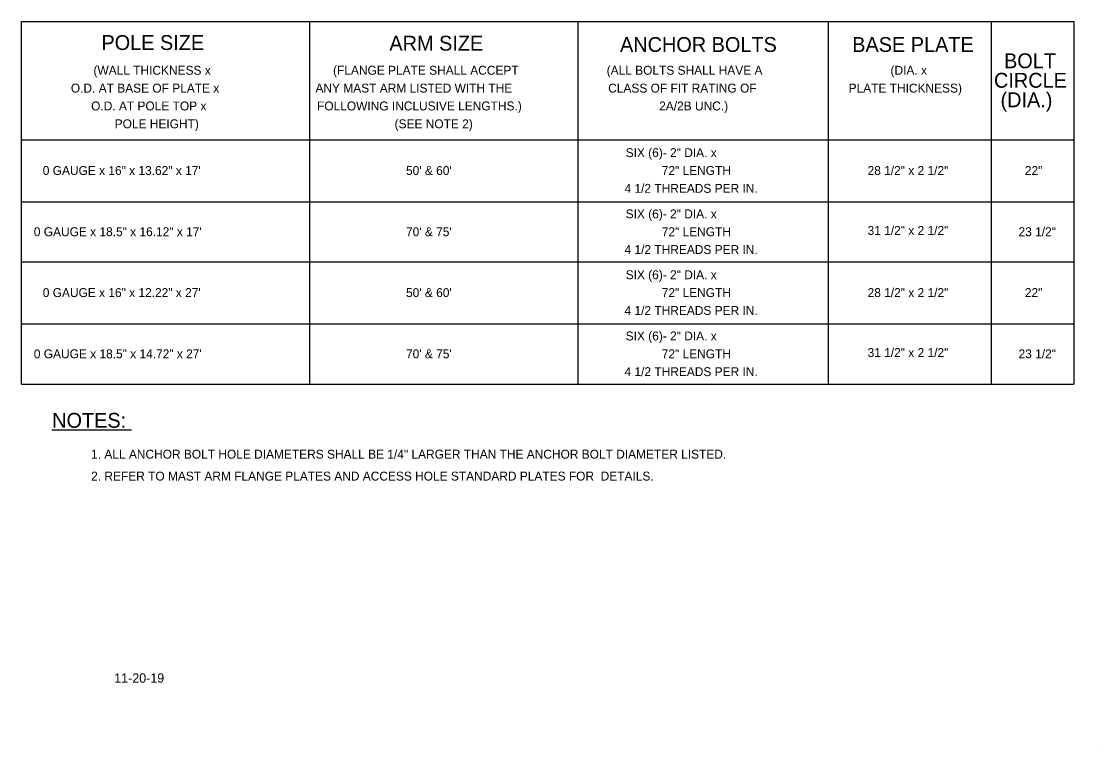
# Model space of a CAD drawing. Extents: x 101.8 to 109.1, y 93.4 to 103.6.
# Drawn here: x 101.85 to 109.09, y 93.43 to 98.31 of the extents above; entities that cross this region are included whole.
import ezdxf

# ---------------------------------------------------------------- set-up
doc = ezdxf.new("R2010")
doc.units = 0
doc.layers.add('DETL-NOTE', color=7, linetype='Continuous')
doc.layers.add('TTLB-TEXT', color=7, linetype='Continuous')

msp = doc.modelspace()

# ---------------------------------------------------------------- linework, layer by layer
at = {"layer": 'DETL-NOTE'}
for p, q in [((101.8456, 95.8723), (101.8456, 98.3099)), ((101.8456, 98.3099), (108.9249, 98.3099)), ((108.9249, 98.3099), (108.9249, 95.8723)), ((102.0486, 95.5651), (102.5862, 95.5651))]:
    msp.add_line(p, q, dxfattribs=at)
for points in [[(103.7832, 98.3099), (103.7832, 95.8723)], [(105.5882, 98.3099), (105.5882, 95.8723)], [(107.2729, 98.3099), (107.2729, 95.8723)], [(108.3684, 98.3097), (108.3684, 95.8723)], [(101.8456, 97.5145), (108.9249, 97.5145)], [(101.8456, 97.0986), (108.9249, 97.0986)], [(101.8456, 96.6934), (108.9249, 96.6934)], [(101.8456, 96.2776), (108.9249, 96.2776)], [(101.8456, 95.8723), (108.9249, 95.8723)]]:
    msp.add_lwpolyline(points, dxfattribs=at)
at = {"layer": 'TTLB-TEXT'}
msp.add_line((109.0914, 93.4283), (109.0914, 93.4283), dxfattribs=at)

# ---------------------------------------------------------------- texts
at = {"layer": 'DETL-NOTE'}
for s, height, p in [('POLE SIZE', 0.1, (102.3831, 98.1186)), ('ARM SIZE', 0.1, (104.3206, 98.1142)), ('ANCHOR BOLTS', 0.1, (105.8724, 98.1055)), ('BASE PLATE', 0.1, (107.4346, 98.1055)), ('BOLT', 0.1, (108.4562, 97.996)), ('(WALL THICKNESS x', 0.06, (102.3295, 97.9522)), ('(FLANGE PLATE SHALL ACCEPT', 0.06, (103.9416, 97.9522)), ('(ALL BOLTS SHALL HAVE A', 0.06, (105.7826, 97.9522)), ('(DIA. x', 0.06, (107.6923, 97.9522)), ('CIRCLE', 0.1, (108.3885, 97.8649)), ('O.D. AT BASE OF PLATE x', 0.06, (102.1775, 97.8322)), ('ANY MAST ARM LISTED WITH THE', 0.06, (103.8232, 97.8322)), ('CLASS OF FIT RATING OF', 0.06, (105.7927, 97.8322)), ('PLATE THICKNESS)', 0.06, (107.4106, 97.8322)), ('(DIA.)', 0.1, (108.4325, 97.7338)), ('O.D. AT POLE TOP x', 0.06, (102.3137, 97.7122)), ('FOLLOWING INCLUSIVE LENGTHS.)', 0.06, (103.8337, 97.7122)), ('2A/2B UNC.)', 0.06, (106.1356, 97.7122)), ('POLE HEIGHT)', 0.06, (102.4722, 97.5922)), ('(SEE NOTE 2)', 0.06, (104.3557, 97.5922)), ('SIX (6)- 2" DIA. x', 0.06, (105.9104, 97.3982)), ('0 GAUGE x 16" x 13.62" x 17\'', 0.06, (101.9884, 97.2782)), ("50' & 60'", 0.06, (104.4326, 97.2782)), ('72" LENGTH', 0.06, (106.1531, 97.2782)), ('28 1/2" x 2 1/2"', 0.06, (107.5381, 97.2782)), ('22"', 0.06, (108.5963, 97.2782)), ('4 1/2 THREADS PER IN.', 0.06, (105.9027, 97.1582)), ('SIX (6)- 2" DIA. x', 0.06, (105.9104, 96.9865)), ('0 GAUGE x 18.5" x 16.12" x 17\'', 0.06, (101.9284, 96.8665)), ("70' & 75'", 0.06, (104.4326, 96.8665)), ('72" LENGTH', 0.06, (106.1531, 96.8665)), ('31 1/2" x 2 1/2"', 0.06, (107.5381, 96.8749)), ('23 1/2"', 0.06, (108.5538, 96.8665)), ('4 1/2 THREADS PER IN.', 0.06, (105.9027, 96.7465)), ('SIX (6)- 2" DIA. x', 0.06, (105.9104, 96.5771)), ('0 GAUGE x 16" x 12.22" x 27\'', 0.06, (101.9884, 96.4571)), ("50' & 60'", 0.06, (104.4326, 96.4571)), ('72" LENGTH', 0.06, (106.1531, 96.4571)), ('28 1/2" x 2 1/2"', 0.06, (107.5381, 96.4571)), ('22"', 0.06, (108.5963, 96.4571)), ('4 1/2 THREADS PER IN.', 0.06, (105.9027, 96.3371)), ('SIX (6)- 2" DIA. x', 0.06, (105.9104, 96.1654)), ('0 GAUGE x 18.5" x 14.72" x 27\'', 0.06, (101.9284, 96.0454)), ("70' & 75'", 0.06, (104.4326, 96.0454)), ('72" LENGTH', 0.06, (106.1531, 96.0454)), ('31 1/2" x 2 1/2"', 0.06, (107.5381, 96.0538)), ('23 1/2"', 0.06, (108.5538, 96.0454)), ('4 1/2 THREADS PER IN.', 0.06, (105.9027, 95.9254)), ('NOTES:', 0.1, (102.0518, 95.5781)), ('1. ALL ANCHOR BOLT HOLE DIAMETERS SHALL BE 1/4" LARGER THAN THE ANCHOR BOLT DIAMETER LISTED.', 0.06, (102.3137, 95.3706)), ('2. REFER TO MAST ARM FLANGE PLATES AND ACCESS HOLE STANDARD PLATES FOR  DETAILS.', 0.06, (102.3137, 95.2231))]:
    msp.add_text(s, height=height, dxfattribs=at).set_placement(p)
at = {"layer": 'TTLB-TEXT'}
msp.add_text('11-20-19', height=0.06282, dxfattribs=at).set_placement((102.4693, 93.864))

doc.saveas('drawing.dxf')
